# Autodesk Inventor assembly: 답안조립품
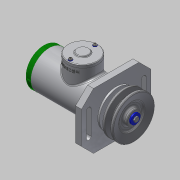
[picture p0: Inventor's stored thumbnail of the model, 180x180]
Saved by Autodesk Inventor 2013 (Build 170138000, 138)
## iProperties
Created: 2017-10
Part Number: 답안조립품
Document SubType Name: Assembly
Designer: dgall
Author: dgall
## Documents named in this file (20)
- C:\Users\dgall\Desktop\471007V1011\답안조립품.iam
- C:\Users\dgall\Desktop\471007V1011\본체.ipt
- C:\Users\dgall\Desktop\471007V1011\볼트 M4 x 10.ipt
- C:\Users\dgall\Desktop\471007V1011\부시1.ipt
- C:\Users\dgall\Desktop\471007V1011\부시2.ipt
- C:\Users\dgall\Desktop\471007V1011\사이드 커버.ipt
- 사이드 커버.ipt
- C:\Users\dgall\Desktop\471007V1011\십자볼트 M3 x 10.ipt
- C:\Users\dgall\Desktop\471007V1011\오일 실 15 25 7.ipt
- C:\Users\dgall\Desktop\471007V1011\와셔 3x6.ipt
- C:\Users\dgall\Desktop\471007V1011\와셔 4x16.ipt
- C:\Users\dgall\Desktop\471007V1011\와셔 10x21.ipt
- C:\Users\dgall\Desktop\471007V1011\축.ipt
- C:\Users\dgall\Desktop\471007V1011\키 4 x 4 x 18.ipt
- C:\Users\dgall\Desktop\471007V1011\탑 커버.ipt
- C:\Users\dgall\Desktop\471007V1011\베어링 15 x 35 x 11.ipt
- C:\Users\dgall\Desktop\471007V1011\멈춤링 35x1.6.ipt
- C:\Users\dgall\Desktop\471007V1011\멈춤링 15 x 1.ipt
- C:\Users\dgall\Desktop\471007V1011\너트 M10.ipt
- C:\Users\dgall\Desktop\471007V1011\V-벨트풀리.ipt
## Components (2 placed, 2 different names)
1. ISO 4017 M4 x 10:1
2. V-벨트풀리:1
